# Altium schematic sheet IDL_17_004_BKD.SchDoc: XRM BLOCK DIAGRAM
size 401 x 291 mm; DocumentNumber: 3; SheetNumber: 3; SheetTotal: 3
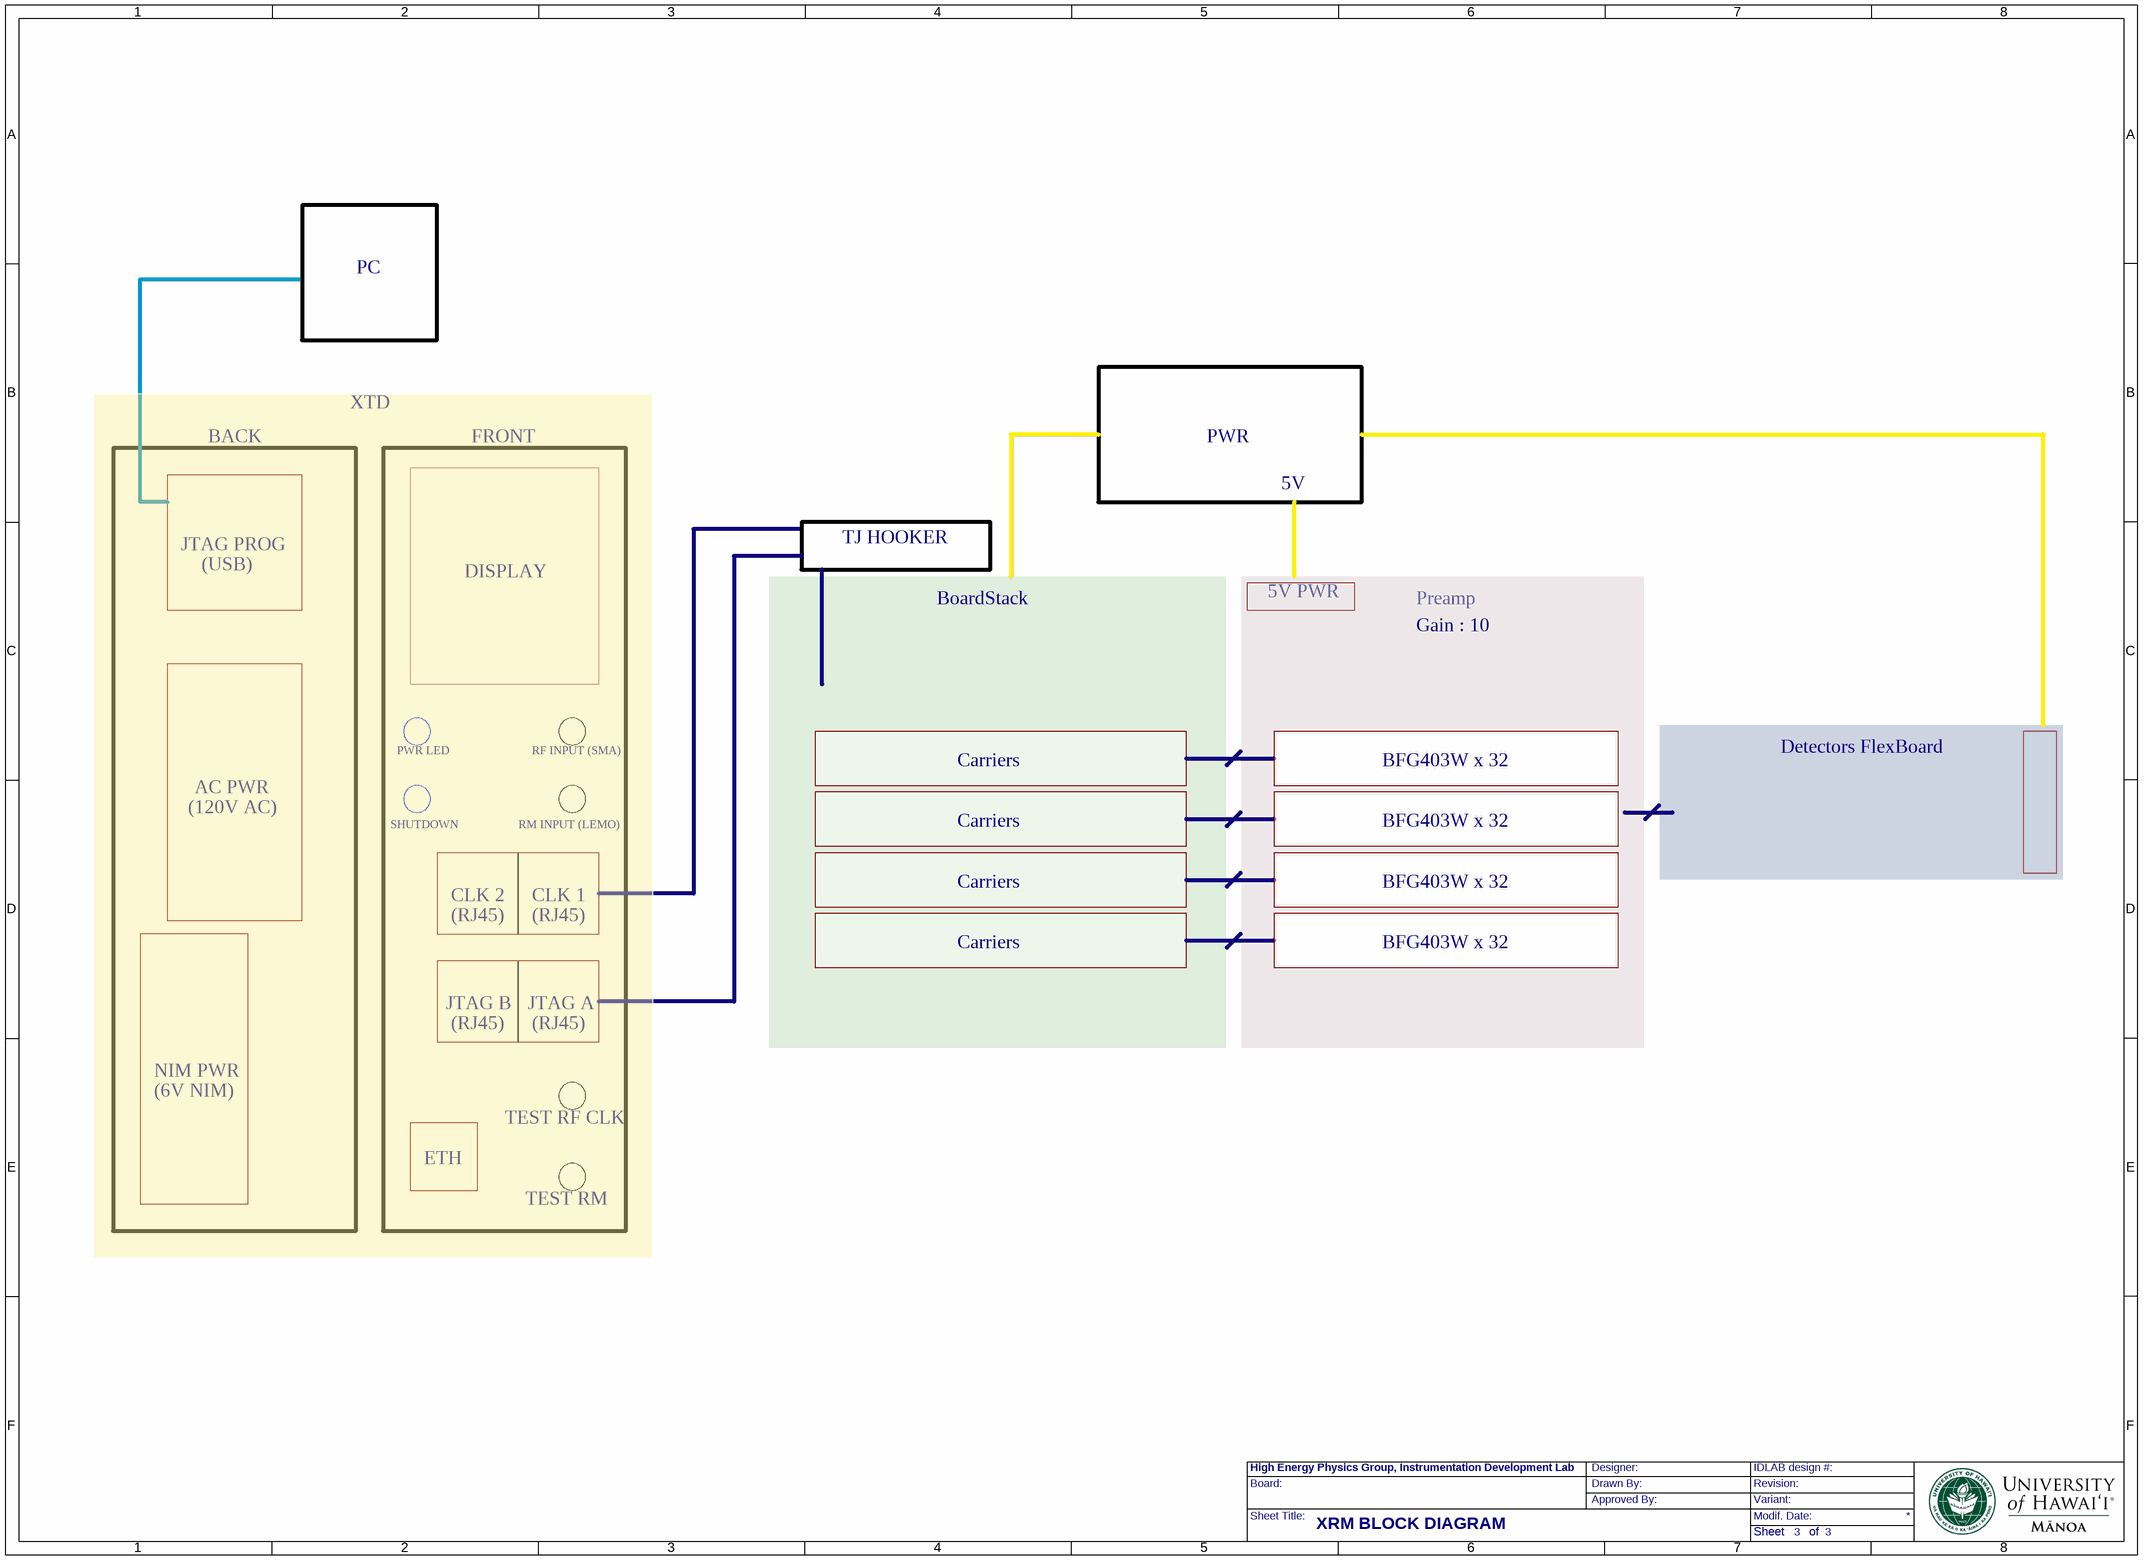
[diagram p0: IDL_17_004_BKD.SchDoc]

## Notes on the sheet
- PC
- XTD
- BACK
- FRONT
- PWR
- 5V
- JTAG PROG
- TJ HOOKER
- (USB)
- DISPLAY
- BoardStack
- 5V PWR
- Preamp
- Gain : 10
- PWR LED
- RF INPUT (SMA)
- Carriers
- BFG403W x 32
- Detectors FlexBoard
- (120V AC)
- AC PWR
- SHUTDOWN
- RM INPUT (LEMO)
- CLK 2
- CLK 1
- (RJ45)
- JTAG B
- JTAG A
- NIM PWR
- (6V NIM)
- ETH
- TEST RF CLK
- TEST RM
